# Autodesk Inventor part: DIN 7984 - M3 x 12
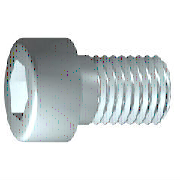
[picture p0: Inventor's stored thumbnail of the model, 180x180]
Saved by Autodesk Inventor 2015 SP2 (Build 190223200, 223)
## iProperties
Created: 2012-02
Part Number: DIN 7984 - M3 x 12
Material: Stahl, weich
Description: Zylinderkopfschraube
Document SubType Name: Modeling
Standard: DIN 7984
Designer: rYan
Standard Revision: 1985
Standards Organization: DIN
Language: de-DE
Size Designation: M3 x 12
Categories: <MemberInstance><Categories><Category DisplayName="Verbindungselemente" InternalName="e4da775c-781d-43d5-af7c-5136215cf5a6" Mnemonic="FSTN"><Category DisplayNam
Density: 7.85 g/cm^3
Mass: 0.985331 g
Surface Area: 2.02025 cm^2
Volume: 0.12552 cm^3
Appearance: Halbpoliert
IsCustomPart: 0
Author: rYan
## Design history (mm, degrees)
sketch "Skizze1"
  geometry: L1 (0.167, 0)-(12, 0); L2 (12, 0)-(12, 1.5); L3 (12, 1.5)-(1.5, 1.5); L4 (1.5, 1.5)-(1.193, 1.5); L5 (1.193, 1.5)-(0, 1.5); L6 (0, 1.5)-(0, 2.75); L7 (0, 2.75)-(-2, 2.75); L8 (-2, 2.75)-(-2, 1.155); L9 (-2, 1.155)-(-0.5, 1.155); L10 (-0.5, 1.155)-(0.167, 0); L11 (-4.8, 0)-(14.8, 0) reference; L12 (0, -0.55)-(0, 3.3) reference; L13 (1.5, 1.5)-(0, 1.5)
  constraints: 22 end point, 6 parallel, 2 collinear, 2 perpendicular, 1 horizontal, 1 point on line
  dimensions: "d1" = 10.5 distance from line of L3.end L2 (= GEL); "d2" = 0.30683 distance of L4.end L3.end (computed from GAL); "d3" = 2 distance between parallel lines of L8 L6 (= KOH); "d4" = 1.5 distance of L8.end L9.end (= INTI); "d5" = 60 deg angle of L10 L1; "d6" = 3 diameter of L3 L1 (= GD); "d7" = 3 diameter of L5 L1 (= BDM); "d8" = 2.3094 diameter of L9 L1 (= 1.1547 x SW); "d9" = 5.5 diameter of L7 L1 (= KOD); "d26" = 12 distance between parallel lines of L12 L2 (= NLG)
revolve "Körper" sketch "Skizze1" stored, may be unused: angle "d10" = 90 deg
sketch "Skizze2"
  geometry: L1 (0, -3.85)-(0, 3.85) reference; L2 (-3.85, 0)-(3.85, 0) reference; L3 (1.155, 0)-(0.577, -1); L4 (0.577, -1)-(-0.577, -1); L5 (-0.577, -1)-(-1.155, 0); L6 (-1.155, 0)-(-0.577, 1); L7 (-0.577, 1)-(0.577, 1); L8 (0.577, 1)-(1.155, 0); 2 further points
  constraints: 12 end point, 1 coincident, 1 horizontal alignment, 1 point on line, 12 other
extrude "Loch" join sketch "Skizze2" stored distance "d11" = 10; taper "d12" = 0 deg
workplane "Work Plane1"
fillet "Fillet2" dims "d30" = 0.1 (= R)
body "Solid1"
fillet "Rundung1" dims "d17" = 0.3 (= RR)
feature "Gewinde" dims "d13" = 10.5 (= GEL), "d14" = 0
chamfer "Fase1" distance "d15" = 0.30673 (= -0.5 x SPD + 0.5 x GD); stored, may be unused: second distance "d16" = 0.30673 (= GUL), angle "d27" = 45 deg
other parameters: "GD" = 3 (= NND) [user parameter; used in 2 equation terms], "NLG" = 12 [user parameter; used in 1 equation term], "GEL" = 10.5 [user parameter; used in 2 equation terms], "KOD" = 5.5 [user parameter; used in 1 equation term], "KOH" = 2 [user parameter; used in 1 equation term], "INTI" = 1.5 [user parameter; used in 1 equation term], "GAL" = 0.30673 (= 0.61345 x PTC) [user parameter; used in 1 equation term], "GUL" = 0.30673 (= 0.61345 x PTC) [user parameter; used in 1 equation term], "BDM" = 3 (= NND) [user parameter; used in 1 equation term], "SW" = 2 [user parameter; used in 2 equation terms], "RR" = 0.3 [user parameter; used in 1 equation term], "SPD" = 2.38655 (= NND - 1.2269 x PTC) [user parameter; used in 1 equation term], "d19" = 0, "d28" = 0, "d29" = 0, "R" = 0.1 [user parameter; used in 1 equation term], "TOA" = 30 deg [user parameter], "GD1" = 2.38655 (= THREADDIA - 1.2269 x PTC) [user parameter], "THREADDIA" = 3 [user parameter; used in 1 equation term], "FAWI" = 45 deg [user parameter], "ANG" = 120 deg [user parameter], "PTC" = 0.5 [user parameter; used in 5 equation terms], "NND" = 3 [user parameter; used in 3 equation terms], "E0" = 2.31 (= 1.155 x SW) [user parameter]
